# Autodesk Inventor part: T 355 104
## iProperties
Company: Mayer & Müller AG Schaltgeräte
Created: 2005-12
Part Number: T 355 104
Material: 2.0402.30
Document SubType Name: Modeling
Designer: I.Baliuc
Manufacturer: Standard
Standards Organization: Custom
Description: Rillenbolzen
Density: 8.2 g/cm^3
HalbzeugNorm: DIN 1756
Abmessung: Rd 8
Author: T.Messerschmitt
Revision Number: 355104
Keywords: 267030
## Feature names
1. Extrusion2
